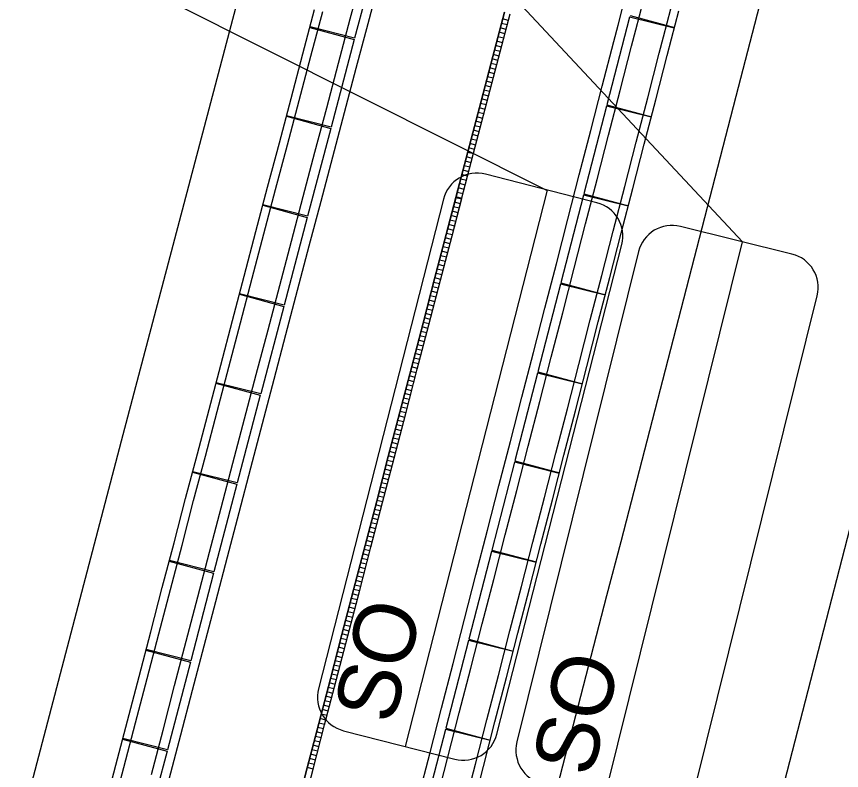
# Model space of a CAD drawing. Extents: x -733601 to -733291, y -1137892 to -1137187.
# Drawn here: x -733436.26 to -733418.32, y -1137623.22 to -1137606.82 of the extents above; entities that cross this region are included whole.
import ezdxf

# ---------------------------------------------------------------- set-up
doc = ezdxf.new("R2010")
doc.units = 0
for name, color, linetype in [('Default', 7, 'Continuous'), ('SIT_PROJ', 7, 'Continuous'), ('SIT_PUV_ZELEZNICE', 7, 'Continuous')]:
    doc.layers.add(name, color=color, linetype=linetype)

# ---------------------------------------------------------------- blocks, each defined once
blk = doc.blocks.new('T_PS_1_1')
at = {"layer": 'Default'}
blk.add_line((-12.486, 3.717), (12.486, 3.717), dxfattribs=at)
for points in [[(10.986, 8), (-10.986, 8)], [(-12.486, 6.5), (-12.486, 1.5)], [(12.486, 1.5), (12.486, 6.5)], [(-10.986, 0), (10.986, 0)]]:
    blk.add_lwpolyline(points, dxfattribs=at)
for centre, start, end in [((-10.986, 6.5), 90, 180), ((10.986, 6.5), 0, 90), ((-10.986, 1.5), 180, 270), ((10.986, 1.5), 270, 360)]:
    blk.add_arc(centre, 1.5, start, end, dxfattribs=at)
blk.add_text('SO', height=2.7, dxfattribs=at).set_placement((-11.75, 4.466))
blk = doc.blocks.new('T_PS_1_1_3')
at = {"layer": 'Default'}
blk.add_line((-0.012486, 0.003717), (0.012486, 0.003717), dxfattribs=at)
for points in [[(0.010986, 0.008), (-0.010986, 0.008)], [(-0.012486, 0.0065), (-0.012486, 0.0015)], [(0.012486, 0.0015), (0.012486, 0.0065)], [(-0.010986, 0), (0.010986, 0)]]:
    blk.add_lwpolyline(points, dxfattribs=at)
for centre, start, end in [((-0.010986, 0.0065), 90, 180), ((0.010986, 0.0065), 0, 90), ((-0.010986, 0.0015), 180, 270), ((0.010986, 0.0015), 270, 360)]:
    blk.add_arc(centre, 0.0015, start, end, dxfattribs=at)
blk.add_text('SO', height=0.0027, dxfattribs=at).set_placement((-0.01175, 0.004466))

msp = doc.modelspace()

# ---------------------------------------------------------------- linework, layer by layer
at = {"layer": 'SIT_PROJ'}
for points in [[(-733445.29, -1137585.169), (-733420.477, -1137611.718), (-733420.477, -1137611.718)], [(-733443.08, -1137601.386), (-733424.737, -1137610.597), (-733424.737, -1137610.597)]]:
    msp.add_lwpolyline(points, dxfattribs=at)
at = {"layer": 'SIT_PUV_ZELEZNICE'}
for p, q in [((-733428.402, -1137605.391), (-733428.907, -1137607.295)), ((-733425.565, -1137606.906), (-733425.69, -1137606.873)), ((-733422.929, -1137606.832), (-733423.422, -1137608.739)), ((-733421.958, -1137607.072), (-733422.929, -1137606.832)), ((-733422.921, -1137606.802), (-733421.956, -1137607.063)), ((-733429.879, -1137607.058), (-733428.914, -1137607.323)), ((-733428.907, -1137607.295), (-733429.876, -1137607.048)), ((-733425.615, -1137607.1), (-733425.741, -1137607.066)), ((-733425.59, -1137607.003), (-733425.716, -1137606.97)), ((-733425.666, -1137607.293), (-733425.791, -1137607.26)), ((-733425.64, -1137607.196), (-733425.766, -1137607.163)), ((-733428.914, -1137607.323), (-733429.419, -1137609.228)), ((-733425.716, -1137607.487), (-733425.842, -1137607.453)), ((-733425.691, -1137607.39), (-733425.817, -1137607.357)), ((-733425.742, -1137607.583), (-733425.867, -1137607.55)), ((-733425.792, -1137607.777), (-733425.918, -1137607.744)), ((-733425.767, -1137607.68), (-733425.893, -1137607.647)), ((-733425.843, -1137607.97), (-733425.969, -1137607.937)), ((-733425.818, -1137607.874), (-733425.943, -1137607.84)), ((-733425.894, -1137608.164), (-733426.019, -1137608.131)), ((-733425.868, -1137608.067), (-733425.994, -1137608.034)), ((-733425.944, -1137608.357), (-733426.07, -1137608.324)), ((-733425.919, -1137608.261), (-733426.045, -1137608.227)), ((-733425.995, -1137608.551), (-733426.12, -1137608.518)), ((-733425.969, -1137608.454), (-733426.095, -1137608.421)), ((-733426.045, -1137608.744), (-733426.171, -1137608.711)), ((-733426.02, -1137608.648), (-733426.146, -1137608.614)), ((-733426.071, -1137608.841), (-733426.196, -1137608.808)), ((-733423.429, -1137608.768), (-733423.922, -1137610.675)), ((-733422.459, -1137609.009), (-733423.429, -1137608.768)), ((-733423.422, -1137608.739), (-733422.456, -1137608.999)), ((-733430.39, -1137608.991), (-733429.426, -1137609.256)), ((-733429.419, -1137609.228), (-733430.388, -1137608.982)), ((-733426.121, -1137609.035), (-733426.247, -1137609.001)), ((-733426.096, -1137608.938), (-733426.222, -1137608.905)), ((-733429.426, -1137609.256), (-733429.929, -1137611.161)), ((-733426.172, -1137609.228), (-733426.297, -1137609.195)), ((-733426.147, -1137609.131), (-733426.272, -1137609.098)), ((-733426.222, -1137609.422), (-733426.348, -1137609.388)), ((-733426.197, -1137609.325), (-733426.323, -1137609.292)), ((-733426.273, -1137609.615), (-733426.399, -1137609.582)), ((-733426.248, -1137609.518), (-733426.373, -1137609.485)), ((-733426.324, -1137609.809), (-733426.449, -1137609.775)), ((-733426.298, -1137609.712), (-733426.424, -1137609.679)), ((-733426.374, -1137610.002), (-733426.5, -1137609.969)), ((-733426.349, -1137609.905), (-733426.474, -1137609.872)), ((-733426.399, -1137610.099), (-733426.525, -1137610.066)), ((-733426.45, -1137610.292), (-733426.576, -1137610.259)), ((-733426.425, -1137610.196), (-733426.55, -1137610.162)), ((-733426.5, -1137610.486), (-733426.626, -1137610.453)), ((-733426.475, -1137610.389), (-733426.601, -1137610.356)), ((-733426.551, -1137610.679), (-733426.677, -1137610.646)), ((-733426.526, -1137610.583), (-733426.651, -1137610.549)), ((-733423.922, -1137610.675), (-733422.957, -1137610.935)), ((-733426.607, -1137610.893), (-733426.733, -1137610.86)), ((-733426.582, -1137610.796), (-733426.707, -1137610.764)), ((-733426.702, -1137610.743), (-733426.576, -1137610.776)), ((-733423.93, -1137610.704), (-733424.423, -1137612.612)), ((-733422.959, -1137610.945), (-733423.93, -1137610.704)), ((-733430.901, -1137610.925), (-733429.937, -1137611.19)), ((-733429.929, -1137611.161), (-733430.899, -1137610.915)), ((-733426.632, -1137610.99), (-733426.758, -1137610.957)), ((-733429.937, -1137611.19), (-733430.439, -1137613.094)), ((-733426.683, -1137611.183), (-733426.808, -1137611.151)), ((-733426.657, -1137611.086), (-733426.783, -1137611.054)), ((-733426.733, -1137611.377), (-733426.859, -1137611.344)), ((-733426.708, -1137611.28), (-733426.834, -1137611.248)), ((-733426.784, -1137611.57), (-733426.91, -1137611.538)), ((-733426.758, -1137611.473), (-733426.884, -1137611.441)), ((-733426.834, -1137611.764), (-733426.96, -1137611.731)), ((-733426.809, -1137611.667), (-733426.935, -1137611.635)), ((-733426.885, -1137611.957), (-733427.011, -1137611.925)), ((-733426.859, -1137611.861), (-733426.985, -1137611.828)), ((-733426.935, -1137612.151), (-733427.061, -1137612.118)), ((-733426.91, -1137612.054), (-733427.036, -1137612.022)), ((-733426.96, -1137612.248), (-733427.086, -1137612.215)), ((-733427.011, -1137612.441), (-733427.137, -1137612.409)), ((-733426.986, -1137612.344), (-733427.112, -1137612.312)), ((-733427.061, -1137612.635), (-733427.187, -1137612.602)), ((-733427.036, -1137612.538), (-733427.162, -1137612.505)), ((-733424.43, -1137612.641), (-733424.923, -1137614.548)), ((-733423.459, -1137612.881), (-733424.43, -1137612.641)), ((-733424.423, -1137612.612), (-733423.457, -1137612.872)), ((-733427.112, -1137612.828), (-733427.238, -1137612.796)), ((-733427.087, -1137612.731), (-733427.213, -1137612.699)), ((-733431.411, -1137612.859), (-733430.447, -1137613.123)), ((-733430.439, -1137613.094), (-733431.409, -1137612.849)), ((-733427.162, -1137613.022), (-733427.288, -1137612.989)), ((-733427.137, -1137612.925), (-733427.263, -1137612.892)), ((-733430.447, -1137613.123), (-733430.948, -1137615.028)), ((-733427.213, -1137613.215), (-733427.339, -1137613.183)), ((-733427.188, -1137613.118), (-733427.314, -1137613.086)), ((-733427.263, -1137613.409), (-733427.389, -1137613.376)), ((-733427.238, -1137613.312), (-733427.364, -1137613.279)), ((-733427.289, -1137613.505), (-733427.414, -1137613.473)), ((-733427.339, -1137613.699), (-733427.465, -1137613.667)), ((-733427.314, -1137613.602), (-733427.44, -1137613.57)), ((-733427.39, -1137613.893), (-733427.515, -1137613.86)), ((-733427.364, -1137613.796), (-733427.49, -1137613.763)), ((-733427.44, -1137614.086), (-733427.566, -1137614.054)), ((-733427.415, -1137613.989), (-733427.541, -1137613.957)), ((-733427.49, -1137614.28), (-733427.616, -1137614.247)), ((-733427.465, -1137614.183), (-733427.591, -1137614.15)), ((-733427.541, -1137614.473), (-733427.667, -1137614.441)), ((-733427.516, -1137614.376), (-733427.642, -1137614.344)), ((-733427.591, -1137614.667), (-733427.717, -1137614.634)), ((-733427.566, -1137614.57), (-733427.692, -1137614.537)), ((-733424.93, -1137614.577), (-733425.423, -1137616.485)), ((-733423.96, -1137614.818), (-733424.93, -1137614.577)), ((-733424.923, -1137614.548), (-733423.957, -1137614.808)), ((-733431.92, -1137614.793), (-733430.956, -1137615.057)), ((-733430.948, -1137615.028), (-733431.918, -1137614.783)), ((-733427.617, -1137614.763), (-733427.742, -1137614.731)), ((-733427.667, -1137614.957), (-733427.793, -1137614.924)), ((-733427.642, -1137614.86), (-733427.768, -1137614.828)), ((-733430.956, -1137615.057), (-733431.456, -1137616.962)), ((-733427.717, -1137615.15), (-733427.843, -1137615.118)), ((-733427.692, -1137615.054), (-733427.818, -1137615.021)), ((-733427.768, -1137615.344), (-733427.894, -1137615.312)), ((-733427.743, -1137615.247), (-733427.869, -1137615.215)), ((-733427.818, -1137615.538), (-733427.944, -1137615.505)), ((-733427.793, -1137615.441), (-733427.919, -1137615.408)), ((-733427.869, -1137615.731), (-733427.995, -1137615.699)), ((-733427.844, -1137615.634), (-733427.969, -1137615.602)), ((-733427.919, -1137615.925), (-733428.045, -1137615.892)), ((-733427.894, -1137615.828), (-733428.02, -1137615.795)), ((-733427.944, -1137616.021), (-733428.07, -1137615.989)), ((-733427.995, -1137616.215), (-733428.121, -1137616.182)), ((-733427.97, -1137616.118), (-733428.095, -1137616.086)), ((-733428.045, -1137616.408), (-733428.171, -1137616.376)), ((-733428.02, -1137616.312), (-733428.146, -1137616.279)), ((-733428.096, -1137616.602), (-733428.222, -1137616.57)), ((-733428.07, -1137616.505), (-733428.196, -1137616.473)), ((-733425.431, -1137616.514), (-733425.923, -1137618.421)), ((-733424.46, -1137616.754), (-733425.431, -1137616.514)), ((-733425.423, -1137616.485), (-733424.457, -1137616.745)), ((-733432.428, -1137616.727), (-733431.464, -1137616.991)), ((-733431.456, -1137616.962), (-733432.426, -1137616.718)), ((-733428.146, -1137616.796), (-733428.272, -1137616.763)), ((-733428.121, -1137616.699), (-733428.247, -1137616.666)), ((-733428.196, -1137616.989), (-733428.322, -1137616.957)), ((-733428.171, -1137616.892), (-733428.297, -1137616.86)), ((-733431.464, -1137616.991), (-733431.963, -1137618.896)), ((-733428.222, -1137617.086), (-733428.348, -1137617.053)), ((-733428.272, -1137617.279), (-733428.398, -1137617.247)), ((-733428.247, -1137617.183), (-733428.373, -1137617.15)), ((-733428.322, -1137617.473), (-733428.448, -1137617.441)), ((-733428.297, -1137617.376), (-733428.423, -1137617.344)), ((-733428.373, -1137617.667), (-733428.499, -1137617.634)), ((-733428.348, -1137617.57), (-733428.473, -1137617.537)), ((-733428.423, -1137617.86), (-733428.549, -1137617.828)), ((-733428.398, -1137617.763), (-733428.524, -1137617.731)), ((-733428.474, -1137618.054), (-733428.599, -1137618.021)), ((-733428.448, -1137617.957), (-733428.574, -1137617.924)), ((-733428.524, -1137618.247), (-733428.65, -1137618.215)), ((-733428.499, -1137618.15), (-733428.625, -1137618.118)), ((-733428.549, -1137618.344), (-733428.675, -1137618.312)), ((-733428.599, -1137618.538), (-733428.725, -1137618.505)), ((-733428.574, -1137618.441), (-733428.7, -1137618.408)), ((-733425.931, -1137618.45), (-733426.424, -1137620.358)), ((-733424.96, -1137618.691), (-733425.931, -1137618.45)), ((-733425.923, -1137618.421), (-733424.958, -1137618.681)), ((-733432.936, -1137618.662), (-733431.971, -1137618.925)), ((-733431.963, -1137618.896), (-733432.933, -1137618.652)), ((-733428.65, -1137618.731), (-733428.776, -1137618.699)), ((-733428.625, -1137618.634), (-733428.751, -1137618.602)), ((-733431.971, -1137618.925), (-733432.47, -1137620.831)), ((-733428.7, -1137618.925), (-733428.826, -1137618.892)), ((-733428.675, -1137618.828), (-733428.801, -1137618.795)), ((-733428.751, -1137619.118), (-733428.876, -1137619.086)), ((-733428.725, -1137619.021), (-733428.851, -1137618.989)), ((-733428.801, -1137619.312), (-733428.927, -1137619.279)), ((-733428.776, -1137619.215), (-733428.902, -1137619.183)), ((-733428.851, -1137619.505), (-733428.977, -1137619.473)), ((-733428.826, -1137619.409), (-733428.952, -1137619.376)), ((-733428.876, -1137619.602), (-733429.002, -1137619.57)), ((-733428.927, -1137619.796), (-733429.053, -1137619.763)), ((-733428.902, -1137619.699), (-733429.027, -1137619.666)), ((-733428.977, -1137619.989), (-733429.103, -1137619.957)), ((-733428.952, -1137619.892), (-733429.078, -1137619.86)), ((-733429.027, -1137620.183), (-733429.153, -1137620.15)), ((-733429.002, -1137620.086), (-733429.128, -1137620.054)), ((-733429.078, -1137620.376), (-733429.204, -1137620.344)), ((-733429.053, -1137620.28), (-733429.179, -1137620.247)), ((-733426.424, -1137620.358), (-733425.458, -1137620.617)), ((-733429.128, -1137620.57), (-733429.254, -1137620.537)), ((-733429.103, -1137620.473), (-733429.229, -1137620.441)), ((-733426.431, -1137620.387), (-733426.924, -1137622.294)), ((-733425.46, -1137620.627), (-733426.431, -1137620.387)), ((-733433.442, -1137620.597), (-733432.477, -1137620.859)), ((-733432.47, -1137620.831), (-733433.44, -1137620.587)), ((-733429.178, -1137620.763), (-733429.304, -1137620.731)), ((-733429.153, -1137620.667), (-733429.279, -1137620.634)), ((-733432.477, -1137620.859), (-733432.976, -1137622.765)), ((-733429.204, -1137620.86), (-733429.329, -1137620.828)), ((-733429.254, -1137621.054), (-733429.38, -1137621.021)), ((-733429.229, -1137620.957), (-733429.355, -1137620.925)), ((-733429.304, -1137621.247), (-733429.43, -1137621.215)), ((-733429.279, -1137621.151), (-733429.405, -1137621.118)), ((-733429.355, -1137621.441), (-733429.48, -1137621.408)), ((-733429.329, -1137621.344), (-733429.455, -1137621.312)), ((-733429.405, -1137621.635), (-733429.531, -1137621.602)), ((-733429.38, -1137621.538), (-733429.506, -1137621.505)), ((-733429.455, -1137621.828), (-733429.581, -1137621.796)), ((-733429.43, -1137621.731), (-733429.556, -1137621.699)), ((-733429.505, -1137622.022), (-733429.631, -1137621.989)), ((-733429.48, -1137621.925), (-733429.606, -1137621.892)), ((-733429.531, -1137622.118), (-733429.657, -1137622.086)), ((-733429.581, -1137622.312), (-733429.707, -1137622.28)), ((-733429.556, -1137622.215), (-733429.682, -1137622.183)), ((-733426.931, -1137622.323), (-733427.424, -1137624.23)), ((-733425.96, -1137622.564), (-733426.931, -1137622.323)), ((-733426.924, -1137622.294), (-733425.958, -1137622.554)), ((-733432.976, -1137622.765), (-733433.946, -1137622.522)), ((-733429.631, -1137622.506), (-733429.757, -1137622.473)), ((-733429.606, -1137622.409), (-733429.732, -1137622.376)), ((-733433.948, -1137622.532), (-733432.983, -1137622.794)), ((-733429.682, -1137622.699), (-733429.807, -1137622.667)), ((-733429.656, -1137622.602), (-733429.782, -1137622.57)), ((-733432.983, -1137622.794), (-733433.481, -1137624.7)), ((-733429.732, -1137622.893), (-733429.858, -1137622.86)), ((-733429.707, -1137622.796), (-733429.833, -1137622.763)), ((-733429.782, -1137623.086), (-733429.908, -1137623.054)), ((-733429.757, -1137622.99), (-733429.883, -1137622.957)), ((-733429.807, -1137623.183), (-733429.933, -1137623.151))]:
    msp.add_line(p, q, dxfattribs=at)
for points in [[(-733459.36, -1137757.582), (-733458.338, -1137753.729), (-733455.783, -1137744.061), (-733453.237, -1137734.391), (-733450.698, -1137724.719), (-733448.167, -1137715.044), (-733445.645, -1137705.368), (-733443.13, -1137695.689), (-733440.624, -1137686.008), (-733440.158, -1137684.204), (-733438.123, -1137676.326), (-733435.622, -1137666.644), (-733433.121, -1137656.962), (-733430.62, -1137647.279), (-733428.119, -1137637.597), (-733425.618, -1137627.915), (-733423.422, -1137619.411), (-733423.117, -1137618.233), (-733420.616, -1137608.551), (-733418.11, -1137598.87), (-733415.599, -1137589.19), (-733413.078, -1137579.513), (-733412.782, -1137578.384)], [(-733453.981, -1137756.29), (-733452.315, -1137749.966), (-733449.778, -1137740.293), (-733447.253, -1137730.617), (-733444.741, -1137720.938), (-733443.633, -1137716.651), (-733442.239, -1137711.256), (-733439.738, -1137701.574), (-733437.237, -1137691.892), (-733434.736, -1137682.209), (-733432.235, -1137672.527), (-733429.735, -1137662.844), (-733427.234, -1137653.162), (-733424.733, -1137643.48), (-733422.232, -1137633.798), (-733419.731, -1137624.116), (-733417.23, -1137614.434), (-733415.895, -1137609.267), (-733414.728, -1137604.752), (-733412.218, -1137595.072), (-733409.698, -1137585.394), (-733408.191, -1137579.632)], [(-733469.582, -1137755.14), (-733468.663, -1137751.534), (-733466.195, -1137741.843), (-733463.726, -1137732.153), (-733461.257, -1137722.462), (-733458.789, -1137712.772), (-733456.32, -1137703.081), (-733453.852, -1137693.391), (-733451.383, -1137683.701), (-733451.044, -1137682.371), (-733448.914, -1137674.01), (-733446.443, -1137664.32), (-733443.966, -1137654.632), (-733441.48, -1137644.946), (-733438.982, -1137635.263), (-733436.47, -1137625.584), (-733433.94, -1137615.909), (-733431.39, -1137606.239), (-733431.038, -1137604.913), (-733428.815, -1137596.577), (-733426.217, -1137586.92), (-733424.808, -1137581.736)], [(-733433.323, -1137623.304), (-733433.071, -1137622.337), (-733432.818, -1137621.37), (-733432.565, -1137620.403), (-733432.312, -1137619.436), (-733432.058, -1137618.469), (-733431.805, -1137617.503), (-733431.551, -1137616.536), (-733431.297, -1137615.569), (-733431.043, -1137614.603), (-733430.789, -1137613.636), (-733430.534, -1137612.67), (-733430.279, -1137611.703), (-733430.024, -1137610.737), (-733429.769, -1137609.771), (-733429.513, -1137608.804), (-733429.258, -1137607.838), (-733429.002, -1137606.872), (-733428.746, -1137605.906)], [(-733432.936, -1137623.405), (-733432.684, -1137622.438), (-733432.431, -1137621.471), (-733432.178, -1137620.504), (-733431.925, -1137619.538), (-733431.671, -1137618.571), (-733431.418, -1137617.604), (-733431.164, -1137616.637), (-733430.91, -1137615.671), (-733430.656, -1137614.704), (-733430.402, -1137613.738), (-733430.147, -1137612.772), (-733429.892, -1137611.805), (-733429.637, -1137610.839), (-733429.382, -1137609.873), (-733429.127, -1137608.907), (-733428.871, -1137607.941), (-733428.615, -1137606.975), (-733428.359, -1137606.009)], [(-733427.517, -1137623.792), (-733427.268, -1137622.825), (-733427.018, -1137621.859), (-733426.768, -1137620.892), (-733426.519, -1137619.926), (-733426.269, -1137618.96), (-733426.019, -1137617.993), (-733425.77, -1137617.027), (-733425.52, -1137616.061), (-733425.271, -1137615.095), (-733425.021, -1137614.128), (-733424.772, -1137613.162), (-733424.522, -1137612.196), (-733424.272, -1137611.23), (-733424.023, -1137610.264), (-733423.773, -1137609.298), (-733423.523, -1137608.332), (-733423.274, -1137607.366), (-733423.181, -1137607.007), (-733423.024, -1137606.4)], [(-733427.13, -1137623.892), (-733426.88, -1137622.925), (-733426.631, -1137621.959), (-733426.381, -1137620.992), (-733426.131, -1137620.026), (-733425.882, -1137619.06), (-733425.632, -1137618.093), (-733425.383, -1137617.127), (-733425.133, -1137616.161), (-733424.883, -1137615.195), (-733424.634, -1137614.229), (-733424.384, -1137613.262), (-733424.135, -1137612.296), (-733423.885, -1137611.33), (-733423.635, -1137610.364), (-733423.386, -1137609.398), (-733423.136, -1137608.432), (-733422.886, -1137607.466), (-733422.793, -1137607.107), (-733422.636, -1137606.5)], [(-733434.35, -1137624.069), (-733434.097, -1137623.102), (-733433.845, -1137622.135), (-733433.592, -1137621.168), (-733433.339, -1137620.201), (-733433.086, -1137619.234), (-733432.832, -1137618.267), (-733432.579, -1137617.3), (-733432.325, -1137616.333), (-733432.071, -1137615.366), (-733431.817, -1137614.399), (-733431.562, -1137613.432), (-733431.308, -1137612.466), (-733431.053, -1137611.499), (-733430.798, -1137610.533), (-733430.542, -1137609.566), (-733430.287, -1137608.6), (-733430.031, -1137607.633), (-733429.775, -1137606.667)], [(-733434.175, -1137624.115), (-733433.923, -1137623.148), (-733433.67, -1137622.18), (-733433.418, -1137621.213), (-733433.165, -1137620.246), (-733432.911, -1137619.279), (-733432.658, -1137618.312), (-733432.405, -1137617.345), (-733432.151, -1137616.378), (-733431.897, -1137615.412), (-733431.643, -1137614.445), (-733431.388, -1137613.478), (-733431.134, -1137612.512), (-733430.879, -1137611.545), (-733430.624, -1137610.579), (-733430.368, -1137609.612), (-733430.113, -1137608.646), (-733429.857, -1137607.68), (-733429.601, -1137606.713)], [(-733430.186, -1137624.123), (-733429.935, -1137623.157), (-733429.683, -1137622.19), (-733429.432, -1137621.223), (-733429.181, -1137620.256), (-733428.93, -1137619.29), (-733428.678, -1137618.323), (-733428.426, -1137617.357), (-733428.175, -1137616.39), (-733427.923, -1137615.424), (-733427.671, -1137614.457), (-733427.419, -1137613.491), (-733427.167, -1137612.524), (-733426.915, -1137611.558), (-733426.663, -1137610.592), (-733426.41, -1137609.626), (-733426.158, -1137608.659), (-733425.905, -1137607.693), (-733425.652, -1137606.727)], [(-733425.652, -1137606.727), (-733425.905, -1137607.693), (-733426.158, -1137608.659), (-733426.41, -1137609.626), (-733426.663, -1137610.592), (-733426.702, -1137610.743), (-733426.576, -1137610.776), (-733426.537, -1137610.625), (-733426.284, -1137609.658), (-733426.032, -1137608.692), (-733425.779, -1137607.726), (-733425.526, -1137606.76)], [(-733426.53, -1137624.047), (-733426.28, -1137623.08), (-733426.03, -1137622.114), (-733425.781, -1137621.147), (-733425.531, -1137620.181), (-733425.281, -1137619.215), (-733425.032, -1137618.248), (-733424.782, -1137617.282), (-733424.533, -1137616.316), (-733424.283, -1137615.35), (-733424.034, -1137614.384), (-733423.784, -1137613.417), (-733423.534, -1137612.451), (-733423.285, -1137611.485), (-733423.035, -1137610.519), (-733422.785, -1137609.553), (-733422.536, -1137608.587), (-733422.286, -1137607.621), (-733422.193, -1137607.262), (-733422.036, -1137606.655)], [(-733426.355, -1137624.092), (-733426.106, -1137623.125), (-733425.856, -1137622.159), (-733425.606, -1137621.192), (-733425.357, -1137620.226), (-733425.107, -1137619.26), (-733424.858, -1137618.294), (-733424.608, -1137617.327), (-733424.358, -1137616.361), (-733424.109, -1137615.395), (-733423.859, -1137614.429), (-733423.61, -1137613.462), (-733423.36, -1137612.496), (-733423.11, -1137611.53), (-733422.861, -1137610.564), (-733422.611, -1137609.598), (-733422.361, -1137608.632), (-733422.112, -1137607.666), (-733422.019, -1137607.307), (-733421.862, -1137606.7)], [(-733430.06, -1137624.156), (-733429.809, -1137623.189), (-733429.558, -1137622.222), (-733429.306, -1137621.256), (-733429.055, -1137620.289), (-733428.804, -1137619.322), (-733428.552, -1137618.356), (-733428.301, -1137617.389), (-733428.049, -1137616.423), (-733427.797, -1137615.456), (-733427.545, -1137614.49), (-733427.293, -1137613.523), (-733427.041, -1137612.557), (-733426.789, -1137611.591), (-733426.537, -1137610.625), (-733426.284, -1137609.658), (-733426.032, -1137608.692), (-733425.779, -1137607.726), (-733425.526, -1137606.76)], [(-733430.06, -1137624.156), (-733429.809, -1137623.189), (-733429.558, -1137622.222), (-733429.306, -1137621.256), (-733429.055, -1137620.289), (-733428.804, -1137619.322), (-733428.552, -1137618.356), (-733428.301, -1137617.389), (-733428.049, -1137616.423), (-733427.797, -1137615.456), (-733427.545, -1137614.49), (-733427.293, -1137613.523), (-733427.041, -1137612.557), (-733426.789, -1137611.591), (-733426.576, -1137610.776), (-733426.702, -1137610.743), (-733426.915, -1137611.558), (-733427.167, -1137612.524), (-733427.419, -1137613.491), (-733427.671, -1137614.457), (-733427.923, -1137615.424), (-733428.175, -1137616.39), (-733428.426, -1137617.357), (-733428.678, -1137618.323), (-733428.93, -1137619.29), (-733429.181, -1137620.256), (-733429.432, -1137621.223), (-733429.683, -1137622.19), (-733429.935, -1137623.157), (-733430.186, -1137624.123)]]:
    msp.add_lwpolyline(points, dxfattribs=at)

# ---------------------------------------------------------------- block references
at = {"layer": 'SIT_PROJ'}
for name, p, xscale, yscale, rotation in [('T_PS_1_1', (-733424.457, -1137617.104), 0.4999999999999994, 0.4999999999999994, 75.68569569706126), ('T_PS_1_1_3', (-733420.175, -1137618.225), 499.99999999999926, 499.99999999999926, 76.07778752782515)]:
    msp.add_blockref(name, p, dxfattribs=dict(at, xscale=xscale, yscale=yscale, rotation=rotation))

doc.saveas('drawing.dxf')
